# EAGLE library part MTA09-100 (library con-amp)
AMP connector
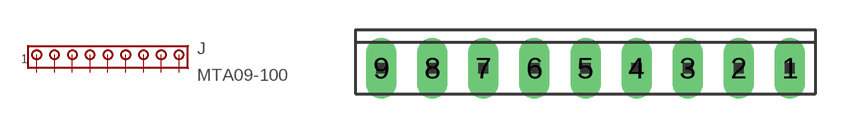
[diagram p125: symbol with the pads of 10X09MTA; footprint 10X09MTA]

Designator prefix J

## MTA09-100 (OC_FARNELL: unknown; OC_NEWARK: unknown)  [10X09MTA]
1  1  pas
2  2  pas
3  3  pas
4  4  pas
5  5  pas
6  6  pas
7  7  pas
8  8  pas
9  9  pas

## Footprint 10X09MTA (pad centres in mm)
AMP MTA connector Source: http://ecommas.tycoelectronics.com .. ENG_CD_640456_W.pdf
drill 1.016 long: 1 10.16,0; 2 7.62,0; 3 5.08,0; 4 2.54,0; 5 0,0; 6 -2.54,0; 7 -5.08,0; 8 -7.62,0; 9 -10.16,0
